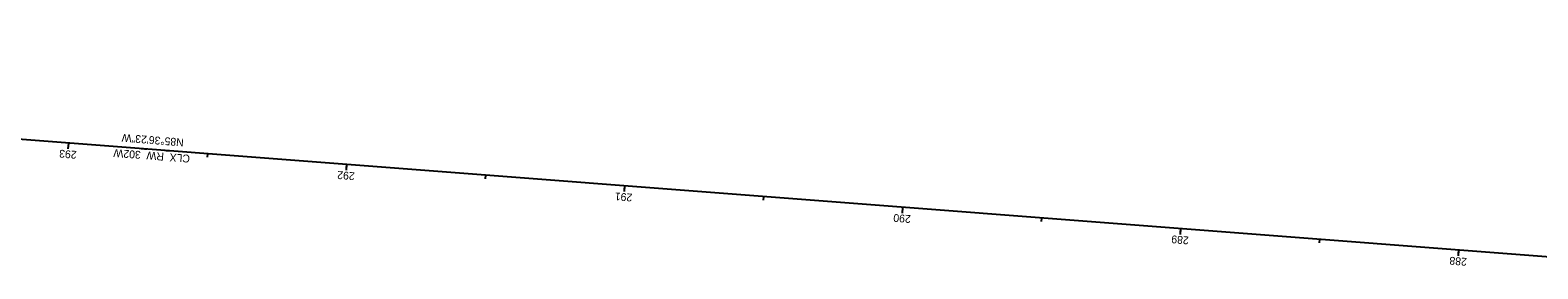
# Model space of a CAD drawing. Extents: x 2045805 to 2050091, y 455249 to 458900.
# Drawn here: x 2046324 to 2046864, y 457269 to 457354 of the extents above; entities that cross this region are included whole.
import ezdxf

# ---------------------------------------------------------------- set-up
doc = ezdxf.new("R2010")
doc.units = 0
for name, color, linetype in [('GE_P_Alignment_100_Cardinal_Points', 7, 'Continuous'), ('GE_P_Alignment_100_Curve_Data', 7, 'Continuous'), ('GE_P_Alignment_100_Stations', 7, 'Continuous'), ('GE_P_Driveway_CL', 7, 'Continuous'), ('PF_X_Ground_Line', 7, 'Continuous'), ('PV_P_EOP', 7, 'Continuous'), ('PV_X_EOP', 7, 'Continuous'), ('RW_X_CL_100_Stations', 7, 'Continuous'), ('SC_Scratch1', 7, 'Continuous'), ('SC_Scratch3', 7, 'Continuous')]:
    doc.layers.add(name, color=color, linetype=linetype)

msp = doc.modelspace()

# ---------------------------------------------------------------- linework, layer by layer
at = {"layer": 'GE_P_Alignment_100_Cardinal_Points'}
for p, q in [((2046337.38, 457313.58), (2046337.23, 457311.59)), ((2046387.24, 457309.75), (2046387.15, 457308.55)), ((2046437.09, 457305.92), (2046436.94, 457303.93)), ((2046486.94, 457302.09), (2046486.85, 457300.89)), ((2046536.8, 457298.26), (2046536.64, 457296.26)), ((2046586.65, 457294.43), (2046586.56, 457293.23)), ((2046636.5, 457290.6), (2046636.35, 457288.6)), ((2046686.36, 457286.77), (2046686.26, 457285.57)), ((2046736.21, 457282.94), (2046736.06, 457280.94)), ((2046786.06, 457279.11), (2046785.97, 457277.91)), ((2046835.92, 457275.28), (2046835.76, 457273.28))]:
    msp.add_line(p, q, dxfattribs=at)
at = {"layer": 'GE_P_Alignment_100_Stations'}
for p, q in [((2046337.38, 457313.58), (2046337.29, 457312.38)), ((2046437.09, 457305.92), (2046437, 457304.72)), ((2046536.8, 457298.26), (2046536.71, 457297.06)), ((2046636.5, 457290.6), (2046636.35, 457288.6)), ((2046736.21, 457282.94), (2046736.12, 457281.74)), ((2046835.92, 457275.28), (2046835.82, 457274.08))]:
    msp.add_line(p, q, dxfattribs=at)
at = {"layer": 'PV_P_EOP'}
msp.add_line((2046922.17, 457268.65), (2045811.12, 457354.01), dxfattribs=at)
at = {"layer": 'PV_X_EOP'}
msp.add_line((2046636.5, 457290.6), (2046636.35, 457288.6), dxfattribs=at)

# ---------------------------------------------------------------- texts
at = {"layer": 'GE_P_Alignment_100_Cardinal_Points'}
for s, p in [('293', (2046340.44, 457310.79)), ('292', (2046440.16, 457303.13)), ('291', (2046539.7, 457295.48)), ('290', (2046639.58, 457287.81)), ('289', (2046739.26, 457280.15)), ('288', (2046838.99, 457272.49))]:
    msp.add_text(s, height=2.8, rotation=175.6064, dxfattribs=at).set_placement(p)
at = {"layer": 'GE_P_Alignment_100_Curve_Data'}
msp.add_text('N85°36\'23"W', height=2.8, rotation=175.6064, dxfattribs=at).set_placement((2046378.84, 457315.21))
at = {"layer": 'GE_P_Alignment_100_Stations'}
msp.add_text('290', height=2.8, rotation=175.6064, dxfattribs=at).set_placement((2046639.58, 457287.81))
at = {"layer": 'GE_P_Driveway_CL'}
msp.add_text('CLX_RW_302W', height=2.8, rotation=175.6064, dxfattribs=at).set_placement((2046381.08, 457309.4))
at = {"layer": 'PF_X_Ground_Line'}
msp.add_text('N85°36\'23"W', height=2.8, rotation=175.6064, dxfattribs=at).set_placement((2046378.84, 457315.21))
at = {"layer": 'PV_X_EOP'}
msp.add_text('290', height=2.8, rotation=175.6064, dxfattribs=at).set_placement((2046639.58, 457287.81))
at = {"layer": 'RW_X_CL_100_Stations'}
msp.add_text('CLX_RW_302W', height=2.8, rotation=175.6064, dxfattribs=at).set_placement((2046381.08, 457309.4))
at = {"layer": 'SC_Scratch1'}
msp.add_text('N85°36\'23"W', height=2.8, rotation=175.6064, dxfattribs=at).set_placement((2046378.84, 457315.21))
at = {"layer": 'SC_Scratch3'}
msp.add_text('CLX_RW_302W', height=2.8, rotation=175.6064, dxfattribs=at).set_placement((2046381.08, 457309.4))

doc.saveas('drawing.dxf')
